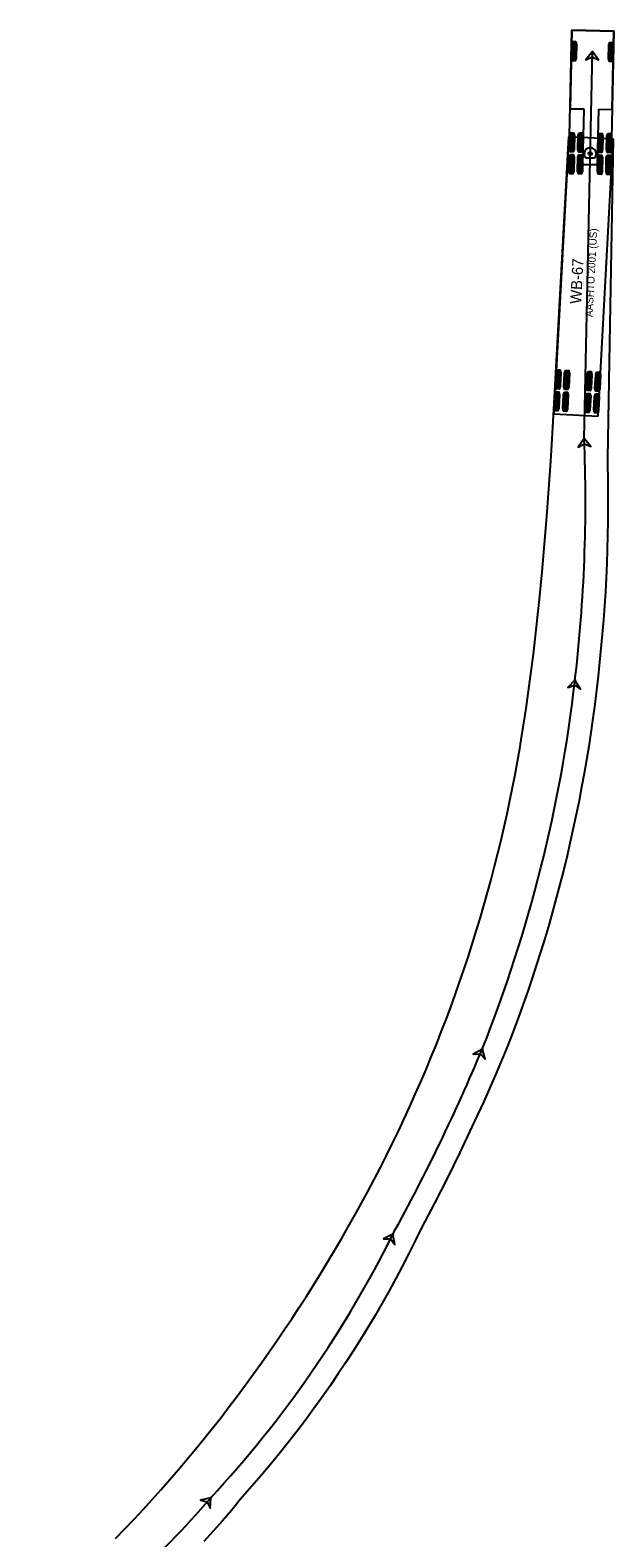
# Model space of a CAD drawing. Extents: x 973688 to 979179, y 703586 to 707602.
# Drawn here: x 979055.7 to 979167, y 705091 to 705379 of the extents above; entities that cross this region are included whole.
import ezdxf

# ---------------------------------------------------------------- set-up
doc = ezdxf.new("R2010")
doc.units = 0
doc.layers.add('0-NPLT', color=7, linetype='Continuous')

msp = doc.modelspace()

# ---------------------------------------------------------------- linework, layer by layer
at = {"layer": '0-NPLT'}
for p, q in [((979159.03, 705378.97), (979158.71, 705363.97)), ((979167.03, 705378.8), (979159.03, 705378.97)), ((979159.03, 705378.97), (979159.03, 705378.97)), ((979166.71, 705363.8), (979167.03, 705378.8)), ((979159.21, 705376.8), (979159.13, 705373.13)), ((979159.44, 705376.79), (979159.36, 705373.13)), ((979159.67, 705376.79), (979159.59, 705373.12)), ((979166.29, 705376.65), (979166.22, 705372.98)), ((979166.52, 705376.64), (979166.45, 705372.98)), ((979166.75, 705376.64), (979166.67, 705372.97)), ((979161.38, 705300.97), (979162.94, 705374.88)), ((979158.71, 705363.97), (979161.28, 705363.92)), ((979161.28, 705363.92), (979161.05, 705353.34)), ((979163.92, 705353.28), (979164.14, 705363.86)), ((979164.14, 705363.86), (979166.71, 705363.8)), ((979158.45, 705358.62), (979155.57, 705305.69)), ((979166.93, 705358.15), (979158.45, 705358.62)), ((979158.45, 705358.62), (979158.45, 705358.62)), ((979158.84, 705359.39), (979158.76, 705355.72)), ((979159.07, 705359.38), (979158.99, 705355.71)), ((979159.3, 705359.38), (979159.22, 705355.71)), ((979160.49, 705359.35), (979160.41, 705355.68)), ((979160.72, 705359.35), (979160.64, 705355.68)), ((979160.95, 705359.34), (979160.87, 705355.67)), ((979164.05, 705305.23), (979166.93, 705358.15)), ((979164.27, 705359.27), (979164.19, 705355.6)), ((979164.5, 705359.26), (979164.42, 705355.6)), ((979164.73, 705359.26), (979164.65, 705355.59)), ((979165.92, 705359.23), (979165.84, 705355.57)), ((979166.15, 705359.23), (979166.07, 705355.56)), ((979166.38, 705359.22), (979166.3, 705355.56)), ((979158.75, 705355.22), (979158.67, 705351.55)), ((979158.98, 705355.21), (979158.9, 705351.55)), ((979159.21, 705355.21), (979159.13, 705351.54)), ((979160.4, 705355.18), (979160.32, 705351.52)), ((979160.63, 705355.18), (979160.55, 705351.51)), ((979160.86, 705355.17), (979160.78, 705351.51)), ((979164.18, 705355.1), (979164.11, 705351.44)), ((979164.41, 705355.1), (979164.34, 705351.43)), ((979164.64, 705355.09), (979164.56, 705351.43)), ((979165.83, 705355.07), (979165.76, 705351.4)), ((979166.06, 705355.06), (979165.98, 705351.4)), ((979166.29, 705355.06), (979166.21, 705351.39)), ((979161.05, 705353.34), (979163.92, 705353.28)), ((979161.7, 705354.6), (979163.32, 705354.56)), ((979156.25, 705314.09), (979156.05, 705310.42)), ((979156.48, 705314.07), (979156.28, 705310.41)), ((979156.71, 705314.06), (979156.51, 705310.4)), ((979157.9, 705314), (979157.7, 705310.33)), ((979158.13, 705313.98), (979157.93, 705310.32)), ((979158.36, 705313.97), (979158.16, 705310.31)), ((979162.18, 705313.76), (979161.98, 705310.1)), ((979162.41, 705313.75), (979162.21, 705310.09)), ((979162.64, 705313.74), (979162.44, 705310.08)), ((979163.83, 705313.67), (979163.63, 705310.01)), ((979164.05, 705313.66), (979163.86, 705310)), ((979164.28, 705313.65), (979164.08, 705309.99)), ((979156.03, 705309.93), (979155.83, 705306.26)), ((979156.26, 705309.91), (979156.06, 705306.25)), ((979156.48, 705309.9), (979156.29, 705306.24)), ((979157.67, 705309.84), (979157.48, 705306.17)), ((979157.9, 705309.82), (979157.7, 705306.16)), ((979158.13, 705309.81), (979157.93, 705306.15)), ((979161.95, 705309.6), (979161.75, 705305.94)), ((979162.18, 705309.59), (979161.98, 705305.93)), ((979162.41, 705309.58), (979162.21, 705305.92)), ((979163.6, 705309.51), (979163.4, 705305.85)), ((979163.83, 705309.5), (979163.63, 705305.84)), ((979164.06, 705309.49), (979163.86, 705305.83)), ((979155.57, 705305.69), (979164.05, 705305.23))]:
    msp.add_line(p, q, dxfattribs=at)
for points in [[(979071.93, 705090.86), (979073.72, 705092.72), (979075.5, 705094.59), (979077.26, 705096.48), (979078.96, 705098.34), (979080.63, 705100.22), (979082.3, 705102.11), (979083.94, 705104.02), (979085.57, 705105.94), (979087.22, 705107.93), (979088.86, 705109.94), (979090.47, 705111.96), (979092.07, 705114), (979093.65, 705116.06), (979095.22, 705118.13), (979096.76, 705120.21), (979098.29, 705122.31), (979099.81, 705124.42), (979101.29, 705126.53), (979102.73, 705128.61), (979104.15, 705130.71), (979105.56, 705132.82), (979106.95, 705134.93), (979108.32, 705137.06), (979109.71, 705139.25), (979111.07, 705141.45), (979112.42, 705143.67), (979113.75, 705145.89), (979115.06, 705148.12), (979116.34, 705150.37), (979117.61, 705152.62), (979118.86, 705154.89), (979120.09, 705157.16), (979121.29, 705159.45), (979122.48, 705161.75), (979123.65, 705164.05), (979124.79, 705166.37), (979125.91, 705168.7), (979127.01, 705171.04), (979128.09, 705173.38), (979129.15, 705175.74), (979130.19, 705178.1), (979131.2, 705180.48), (979132.19, 705182.86), (979133.16, 705185.25), (979134.11, 705187.66), (979135.02, 705190.02), (979135.9, 705192.38), (979136.76, 705194.74), (979137.6, 705197.12), (979138.41, 705199.5), (979139.22, 705201.93), (979140.01, 705204.38), (979140.78, 705206.85), (979141.53, 705209.32), (979142.25, 705211.79), (979142.95, 705214.28), (979143.63, 705216.77), (979144.28, 705219.27), (979144.91, 705221.77), (979145.52, 705224.28), (979146.1, 705226.79), (979146.66, 705229.31), (979147.2, 705231.82), (979147.7, 705234.29), (979148.18, 705236.77), (979148.64, 705239.25), (979149.08, 705241.74), (979149.5, 705244.26), (979150.3, 705249.41), (979151.03, 705254.6), (979151.69, 705259.8), (979152.3, 705265.02), (979152.85, 705270.26), (979153.36, 705275.52), (979153.82, 705280.78), (979154.25, 705286.05), (979154.64, 705291.33), (979155, 705296.62), (979155.34, 705301.91), (979155.93, 705312.28), (979158.45, 705358.62), (979158.6, 705358.81), (979159.03, 705378.97), (979167.03, 705378.8), (979166.59, 705358.24), (979166.93, 705358.15), (979166.15, 705315.62), (979165.83, 705297.24), (979165.83, 705295.9), (979165.88, 705293.21), (979165.91, 705290.53), (979165.91, 705287.84), (979165.89, 705285.15), (979165.84, 705282.46), (979165.77, 705279.77), (979165.67, 705277.08), (979165.55, 705274.39), (979165.41, 705271.7), (979165.24, 705269.01), (979165.05, 705266.32), (979164.83, 705263.63), (979164.58, 705260.95), (979164.03, 705255.57), (979163.73, 705252.89), (979163.39, 705250.21), (979163.03, 705247.53), (979162.65, 705244.85), (979162.24, 705242.17), (979161.81, 705239.56), (979161.36, 705236.96), (979160.89, 705234.36), (979160.39, 705231.77), (979159.86, 705229.18), (979159.3, 705226.56), (979158.72, 705223.92), (979158.11, 705221.29), (979157.47, 705218.67), (979156.8, 705216.05), (979156.12, 705213.44), (979155.4, 705210.83), (979154.66, 705208.24), (979153.9, 705205.65), (979153.11, 705203.06), (979152.3, 705200.49), (979151.46, 705197.92), (979150.6, 705195.39), (979149.74, 705192.9), (979148.84, 705190.42), (979147.47, 705186.71), (979146.47, 705184.27), (979144.38, 705179.32), (979142.2, 705174.37), (979139.96, 705169.47), (979137.65, 705164.59), (979135.28, 705159.75), (979132.83, 705154.95), (979130.32, 705150.18), (979129.15, 705147.75), (979127.94, 705145.33), (979126.7, 705142.93), (979125.44, 705140.55), (979124.14, 705138.18), (979122.82, 705135.82), (979121.46, 705133.48), (979120.08, 705131.16), (979118.68, 705128.88), (979117.27, 705126.65), (979115.84, 705124.43), (979114.38, 705122.23), (979112.89, 705120.05), (979111.37, 705117.87), (979109.79, 705115.67), (979108.18, 705113.49), (979106.54, 705111.33), (979104.88, 705109.19), (979103.19, 705107.07), (979101.48, 705104.97), (979099.74, 705102.9), (979097.98, 705100.84), (979095.74, 705098.31), (979094.06, 705096.25), (979092.35, 705094.24), (979090.6, 705092.26), (979088.82, 705090.31)], [(979162.94, 705374.88), (979161.69, 705373.32), (979162.92, 705373.88), (979164.13, 705373.27), (979162.94, 705374.88)], [(979161.38, 705300.97), (979160.22, 705299.34), (979161.42, 705299.97), (979162.66, 705299.44), (979161.38, 705300.97)], [(979159.62, 705254.83), (979158.23, 705253.39), (979159.51, 705253.84), (979160.65, 705253.12), (979159.62, 705254.83)], [(979141.94, 705184.36), (979140.2, 705183.37), (979141.55, 705183.44), (979142.45, 705182.43), (979141.94, 705184.36)], [(979124.87, 705148.97), (979123.07, 705148.09), (979124.42, 705148.08), (979125.25, 705147.01), (979124.87, 705148.97)], [(979090.11, 705098.64), (979088.16, 705098.21), (979089.46, 705097.87), (979090.02, 705096.64), (979090.11, 705098.64)]]:
    msp.add_lwpolyline(points, dxfattribs=at)
for points in [[(979159.16, 705376.8), (979159.73, 705376.79), (979159.89, 705376.27), (979159.83, 705373.63), (979159.65, 705373.12), (979159.08, 705373.13), (979158.92, 705373.65), (979158.97, 705376.29)], [(979166.24, 705376.65), (979166.81, 705376.64), (979166.97, 705376.12), (979166.91, 705373.48), (979166.73, 705372.97), (979166.16, 705372.98), (979166, 705373.5), (979166.05, 705376.14)], [(979162.94, 705374.88), (979161.69, 705373.32), (979162.92, 705373.88), (979164.13, 705373.27)], [(979158.78, 705359.39), (979159.36, 705359.37), (979159.52, 705358.86), (979159.46, 705356.22), (979159.28, 705355.71), (979158.71, 705355.72), (979158.54, 705356.24), (979158.6, 705358.88)], [(979160.43, 705359.35), (979161.01, 705359.34), (979161.17, 705358.82), (979161.11, 705356.18), (979160.93, 705355.67), (979160.36, 705355.69), (979160.19, 705356.2), (979160.25, 705358.84)], [(979164.22, 705359.27), (979164.79, 705359.26), (979164.95, 705358.74), (979164.89, 705356.1), (979164.71, 705355.59), (979164.14, 705355.6), (979163.98, 705356.12), (979164.03, 705358.76)], [(979165.87, 705359.24), (979166.44, 705359.22), (979166.6, 705358.71), (979166.54, 705356.07), (979166.36, 705355.56), (979165.79, 705355.57), (979165.63, 705356.09), (979165.68, 705358.73)], [(979158.7, 705355.22), (979159.27, 705355.21), (979159.43, 705354.69), (979159.37, 705352.05), (979159.19, 705351.54), (979158.62, 705351.55), (979158.46, 705352.07), (979158.51, 705354.71)], [(979160.34, 705355.19), (979160.92, 705355.17), (979161.08, 705354.66), (979161.02, 705352.02), (979160.84, 705351.51), (979160.27, 705351.52), (979160.11, 705352.04), (979160.16, 705354.68)], [(979164.13, 705355.1), (979164.7, 705355.09), (979164.86, 705354.58), (979164.8, 705351.94), (979164.62, 705351.43), (979164.05, 705351.44), (979163.89, 705351.96), (979163.94, 705354.6)], [(979165.78, 705355.07), (979166.35, 705355.06), (979166.51, 705354.54), (979166.45, 705351.9), (979166.27, 705351.39), (979165.7, 705351.4), (979165.54, 705351.92), (979165.59, 705354.56)], [(979156.2, 705314.09), (979156.77, 705314.06), (979156.91, 705313.54), (979156.77, 705310.9), (979156.57, 705310.4), (979156, 705310.43), (979155.85, 705310.95), (979156, 705313.59)], [(979157.84, 705314), (979158.42, 705313.97), (979158.56, 705313.45), (979158.42, 705310.81), (979158.22, 705310.31), (979157.65, 705310.34), (979157.5, 705310.86), (979157.64, 705313.5)], [(979162.12, 705313.77), (979162.69, 705313.74), (979162.84, 705313.21), (979162.69, 705310.58), (979162.49, 705310.07), (979161.92, 705310.11), (979161.78, 705310.63), (979161.92, 705313.26)], [(979163.77, 705313.68), (979164.34, 705313.65), (979164.48, 705313.12), (979164.34, 705310.49), (979164.14, 705309.98), (979163.57, 705310.02), (979163.43, 705310.54), (979163.57, 705313.17)], [(979155.97, 705309.93), (979156.54, 705309.9), (979156.69, 705309.38), (979156.54, 705306.74), (979156.34, 705306.24), (979155.77, 705306.27), (979155.63, 705306.79), (979155.77, 705309.42)], [(979157.62, 705309.84), (979158.19, 705309.81), (979158.33, 705309.29), (979158.19, 705306.65), (979157.99, 705306.15), (979157.42, 705306.18), (979157.27, 705306.7), (979157.42, 705309.34)], [(979161.89, 705309.61), (979162.47, 705309.57), (979162.61, 705309.05), (979162.47, 705306.42), (979162.27, 705305.91), (979161.7, 705305.94), (979161.55, 705306.47), (979161.69, 705309.1)], [(979163.54, 705309.52), (979164.11, 705309.49), (979164.26, 705308.96), (979164.11, 705306.33), (979163.91, 705305.82), (979163.34, 705305.85), (979163.2, 705306.38), (979163.34, 705309.01)], [(979161.38, 705300.97), (979160.22, 705299.34), (979161.42, 705299.97), (979162.66, 705299.44)], [(979159.62, 705254.83), (979158.23, 705253.39), (979159.51, 705253.84), (979160.65, 705253.12)], [(979141.94, 705184.36), (979140.2, 705183.37), (979141.55, 705183.44), (979142.45, 705182.43)], [(979124.87, 705148.97), (979123.07, 705148.09), (979124.42, 705148.08), (979125.25, 705147.01)], [(979090.11, 705098.64), (979088.16, 705098.21), (979089.46, 705097.87), (979090.02, 705096.64)]]:
    msp.add_lwpolyline(points, close=True, dxfattribs=at)
for centre, radius in [((979162.94, 705374.88), 0.0417), ((979162.53, 705355.39), 0.34), ((979161.38, 705300.97), 0.0417), ((979161.38, 705300.97), 0.0417), ((979159.62, 705254.83), 0.0417), ((979159.62, 705254.83), 0.0417), ((979141.94, 705184.36), 0.0417), ((979141.94, 705184.36), 0.0417), ((979124.87, 705148.97), 0.0417), ((979124.87, 705148.97), 0.0417), ((979090.11, 705098.64), 0.0417), ((979090.11, 705098.64), 0.0417)]:
    msp.add_circle(centre, radius, dxfattribs=at)
for centre, radius, start, end in [((979162.53, 705355.39), 1.14, 313.7782, 223.7782), ((978871.43, 705288.88), 290.19, 353.261, 2.3873), ((978886.66, 705285.87), 274.72, 338.3146, 353.5122), ((978792.47, 705331.16), 379.05, 331.2731, 337.2148), ((978933.4, 705244.02), 213.76, 317.1489, 333.601), ((978982.03, 705189.62), 141.27, 301.4101, 319.9095)]:
    msp.add_arc(centre, radius, start, end, dxfattribs=at)

# ---------------------------------------------------------------- texts
for s, height, p in [('AASHTO 2001 (US)', 1.4167, (979162.96, 705324.15)), ('WB-67', 2.125, (979160.79, 705326.63)), ('(c) 2022 Transoft Solutions, Inc. All rights reserved.', 0.085, (979161.2, 705330.18))]:
    msp.add_text(s, height=height, rotation=86.8859, dxfattribs=at).set_placement(p)

doc.saveas('drawing.dxf')
